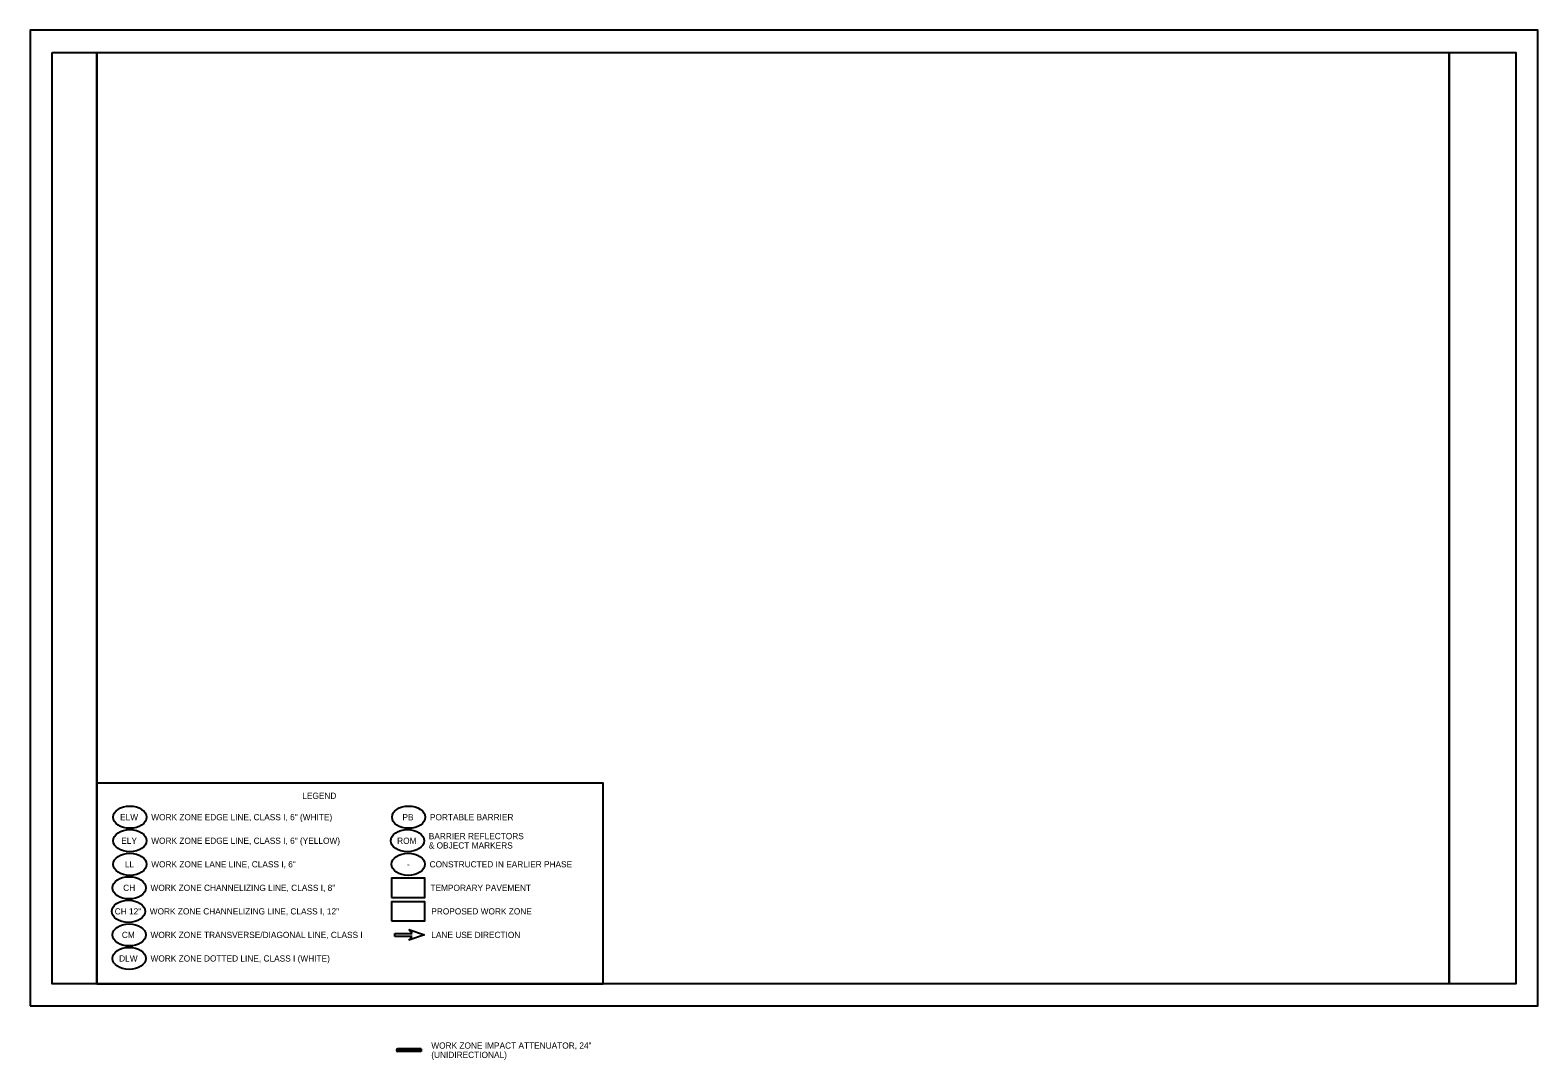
# Model space of a CAD drawing. Extents: x 0 to 34, y -1.2 to 22.
import ezdxf

# ---------------------------------------------------------------- set-up
doc = ezdxf.new("R2010")
doc.units = 0
for name, color, linetype in [('DR_X_Ditch', 7, 'Continuous'), ('DR_X_Elev_Flow', 7, 'Continuous'), ('RD_X_Fence', 7, 'Continuous'), ('SG_X_Manhole', 7, 'Continuous'), ('SV_X_Occupation_Line', 7, 'Continuous'), ('SV_X_Shot_Marker', 7, 'Continuous')]:
    doc.layers.add(name, color=color, linetype=linetype)

msp = doc.modelspace()

# ---------------------------------------------------------------- linework, layer by layer
at = {"layer": 'DR_X_Ditch'}
msp.add_lwpolyline([(8.151, 1.916), (8.901, 1.916), (8.901, 2.348), (8.151, 2.348)], close=True, dxfattribs=at)
at = {"layer": 'DR_X_Elev_Flow'}
msp.add_line((32, 0.5), (32, 21.5), dxfattribs=at)
for points in [[(0, 0), (34, 0), (34, 22), (0, 22)], [(0.5, 21.5), (1.5, 21.5), (1.5, 0.5), (0.5, 0.5)], [(1.5, 21.5), (33.5, 21.5), (33.5, 0.5), (1.5, 0.5)]]:
    msp.add_lwpolyline(points, close=True, dxfattribs=at)
at = {"layer": 'RD_X_Fence'}
msp.add_lwpolyline([(8.151, 2.447), (8.901, 2.447), (8.901, 2.878), (8.151, 2.878)], close=True, dxfattribs=at)
at = {"layer": 'SG_X_Manhole'}
msp.add_lwpolyline([(1.5, 0.5), (12.923, 0.5), (12.923, 5.025), (1.5, 5.025)], close=True, dxfattribs=at)
at = {"layer": 'SV_X_Occupation_Line'}
for p, q in [((8.816, -0.966), (8.293, -0.966)), ((8.293, -1.027), (8.315, -0.966)), ((8.315, -1.027), (8.293, -0.966)), ((8.337, -1.027), (8.359, -0.966)), ((8.359, -1.027), (8.337, -0.966)), ((8.381, -1.027), (8.402, -0.966)), ((8.402, -1.027), (8.381, -0.966)), ((8.424, -1.027), (8.446, -0.966)), ((8.446, -1.027), (8.424, -0.966)), ((8.468, -1.027), (8.49, -0.966)), ((8.49, -1.027), (8.468, -0.966)), ((8.512, -1.027), (8.534, -0.966)), ((8.534, -1.027), (8.512, -0.966)), ((8.555, -1.027), (8.577, -0.966)), ((8.577, -1.027), (8.555, -0.966)), ((8.599, -1.027), (8.621, -0.966)), ((8.621, -1.027), (8.599, -0.966)), ((8.643, -1.027), (8.665, -0.966)), ((8.665, -1.027), (8.643, -0.966)), ((8.686, -1.027), (8.708, -0.966)), ((8.708, -1.027), (8.686, -0.966)), ((8.73, -1.027), (8.752, -0.966)), ((8.752, -1.027), (8.73, -0.966)), ((8.774, -1.027), (8.796, -0.966)), ((8.796, -1.027), (8.774, -0.966)), ((8.816, -0.966), (8.816, -1.027)), ((8.816, -1.027), (8.293, -1.027))]:
    msp.add_line(p, q, dxfattribs=at)
msp.add_arc((8.293, -0.996), 0.0304, 90.0014, 270.0014, dxfattribs=at)
at = {"layer": 'SV_X_Shot_Marker'}
for p, q in [((8.612, 1.636), (8.542, 1.722)), ((8.542, 1.722), (8.892, 1.601)), ((8.227, 1.566), (8.227, 1.636)), ((8.227, 1.636), (8.612, 1.636)), ((8.227, 1.601), (8.227, 1.601)), ((8.612, 1.566), (8.227, 1.566)), ((8.892, 1.601), (8.542, 1.479)), ((8.542, 1.479), (8.612, 1.566)), ((8.892, 1.601), (8.892, 1.601))]:
    msp.add_line(p, q, dxfattribs=at)
msp.add_lwpolyline([(1.5, 21.5), (32, 21.5), (32, 0.5), (1.5, 0.5)], close=True, dxfattribs=at)
for centre in [(2.249, 4.255), (8.535, 4.255), (2.249, 3.724), (8.508, 3.724), (2.249, 3.193), (8.526, 3.193), (2.232, 2.662), (2.216, 2.132), (2.232, 1.601), (2.232, 1.07)]:
    msp.add_ellipse(centre, major_axis=(0.375, 0), ratio=0.666667, dxfattribs=at)

# ---------------------------------------------------------------- texts
for s, p in [('LEGEND', (6.136, 4.668)), ('ELW', (2.029, 4.185)), ('WORK ZONE EDGE LINE, CLASS I, 6" (WHITE)', (2.73, 4.185)), ('PB', (8.396, 4.185)), ('PORTABLE BARRIER', (9.016, 4.185)), ('ELY', (2.055, 3.654)), ('WORK ZONE EDGE LINE, CLASS I, 6" (YELLOW)', (2.73, 3.654)), ('ROM', (8.276, 3.654)), ('BARRIER REFLECTORS', (8.989, 3.758)), ('& OBJECT MARKERS', (8.989, 3.548)), ('LL', (2.135, 3.123)), ('WORK ZONE LANE LINE, CLASS I, 6"', (2.73, 3.123)), ('-', (8.495, 3.123)), ('CONSTRUCTED IN EARLIER PHASE', (9.008, 3.123)), ('CH', (2.098, 2.592)), ('WORK ZONE CHANNELIZING LINE, CLASS I, 8"', (2.714, 2.592)), ('TEMPORARY PAVEMENT', (9.027, 2.592)), ('CH 12"', (1.907, 2.062)), ('WORK ZONE CHANNELIZING LINE, CLASS I, 12"', (2.697, 2.062)), ('PROPOSED WORK ZONE', (9.046, 2.062)), ('CM', (2.068, 1.531)), ('WORK ZONE TRANSVERSE/DIAGONAL LINE, CLASS I', (2.714, 1.531)), ('LANE USE DIRECTION', (9.046, 1.531)), ('DLW', (2.007, 1)), ('WORK ZONE DOTTED LINE, CLASS I (WHITE)', (2.714, 1)), ('WORK ZONE IMPACT ATTENUATOR, 24"', (9.046, -0.964)), ('(UNIDIRECTIONAL)', (9.046, -1.174))]:
    msp.add_text(s, height=0.14, dxfattribs=at).set_placement(p)

doc.saveas('drawing.dxf')
